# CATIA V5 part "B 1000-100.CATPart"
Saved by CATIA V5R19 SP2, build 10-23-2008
Part number: B 1000-100
Bounding box of the stored display mesh (mm): x -24.865 to 24.865, y -24.997 to 24.997, z 0 to 295
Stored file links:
  C:\Users\Bora\Desktop\3D Katı model\B serisi\B 1000\B 1000-100.CATPart
  C:\Program Files\Dassault Systemes\B19\intel_a\reffiles\standard\MetricThickPitch.txt
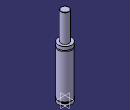
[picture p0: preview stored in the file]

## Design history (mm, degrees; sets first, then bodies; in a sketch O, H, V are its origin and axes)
Body1 (main body)
  Sketch1 on yz-plane, origin (0, 0, 0), H (0, 1, 0), V (0, 0, 1)
    point P1 (25, 179.5)
    point P2 (25, 175.5)
    point P3 (25, 179.5)
    point P6 (25, 175.5)
    point P9 (15, 294)
    point P11 (15, 294)
    arc A1 centre (25, 177.5) radius 2 from (25, 179.5) to (25, 175.5) ccw
    line L1 (25, 179.5) -> (25, 192)
    line L2 (25, 13) -> (25, 175.5)
    line L3 (21.5, 13) -> (21.5, 8)
    arc A2 centre (14, 294) radius 1 from (15, 294) to (14, 295) ccw
    line L4 (15, 294) -> (15, 192)
    line L5 (25, 0) -> (25, 8)
    line L6 (14, 295) -> (0, 295)
    point P15 (0, 295)
    line L7 (15, 192) -> (25, 192)
    line L8 (0, 0) -> (25, 0)
    line L9 (21.5, 13) -> (25, 13)
    line L10 (21.5, 8) -> (25, 8)
    coincidence: P15 V, P1 P3, P2 P6, P9 P11
    tangency: L6 A2
    horizontal: L7 H, L8 H, L9 H, L10 H
  Shaft1: profile Sketch1, axis Sketch1.V, angle 360
  Sketch2 on face of Shaft1 from Sketch1.L8, origin (0, 0, 0), H (1, 0, 0), V (0, -1, 0)
    point P1 (10, 0)
    distance P1 V = 10
  Hole1: placed by Sketch2, at (10, 0, 0) direction (0, 0, 1), diameter 6.647, depth 13, threaded "M8", thread diameter 8, thread depth 13, pitch 1.25
  CircPattern1: of Hole1, instances 2, angular step 180, axis from xy-plane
